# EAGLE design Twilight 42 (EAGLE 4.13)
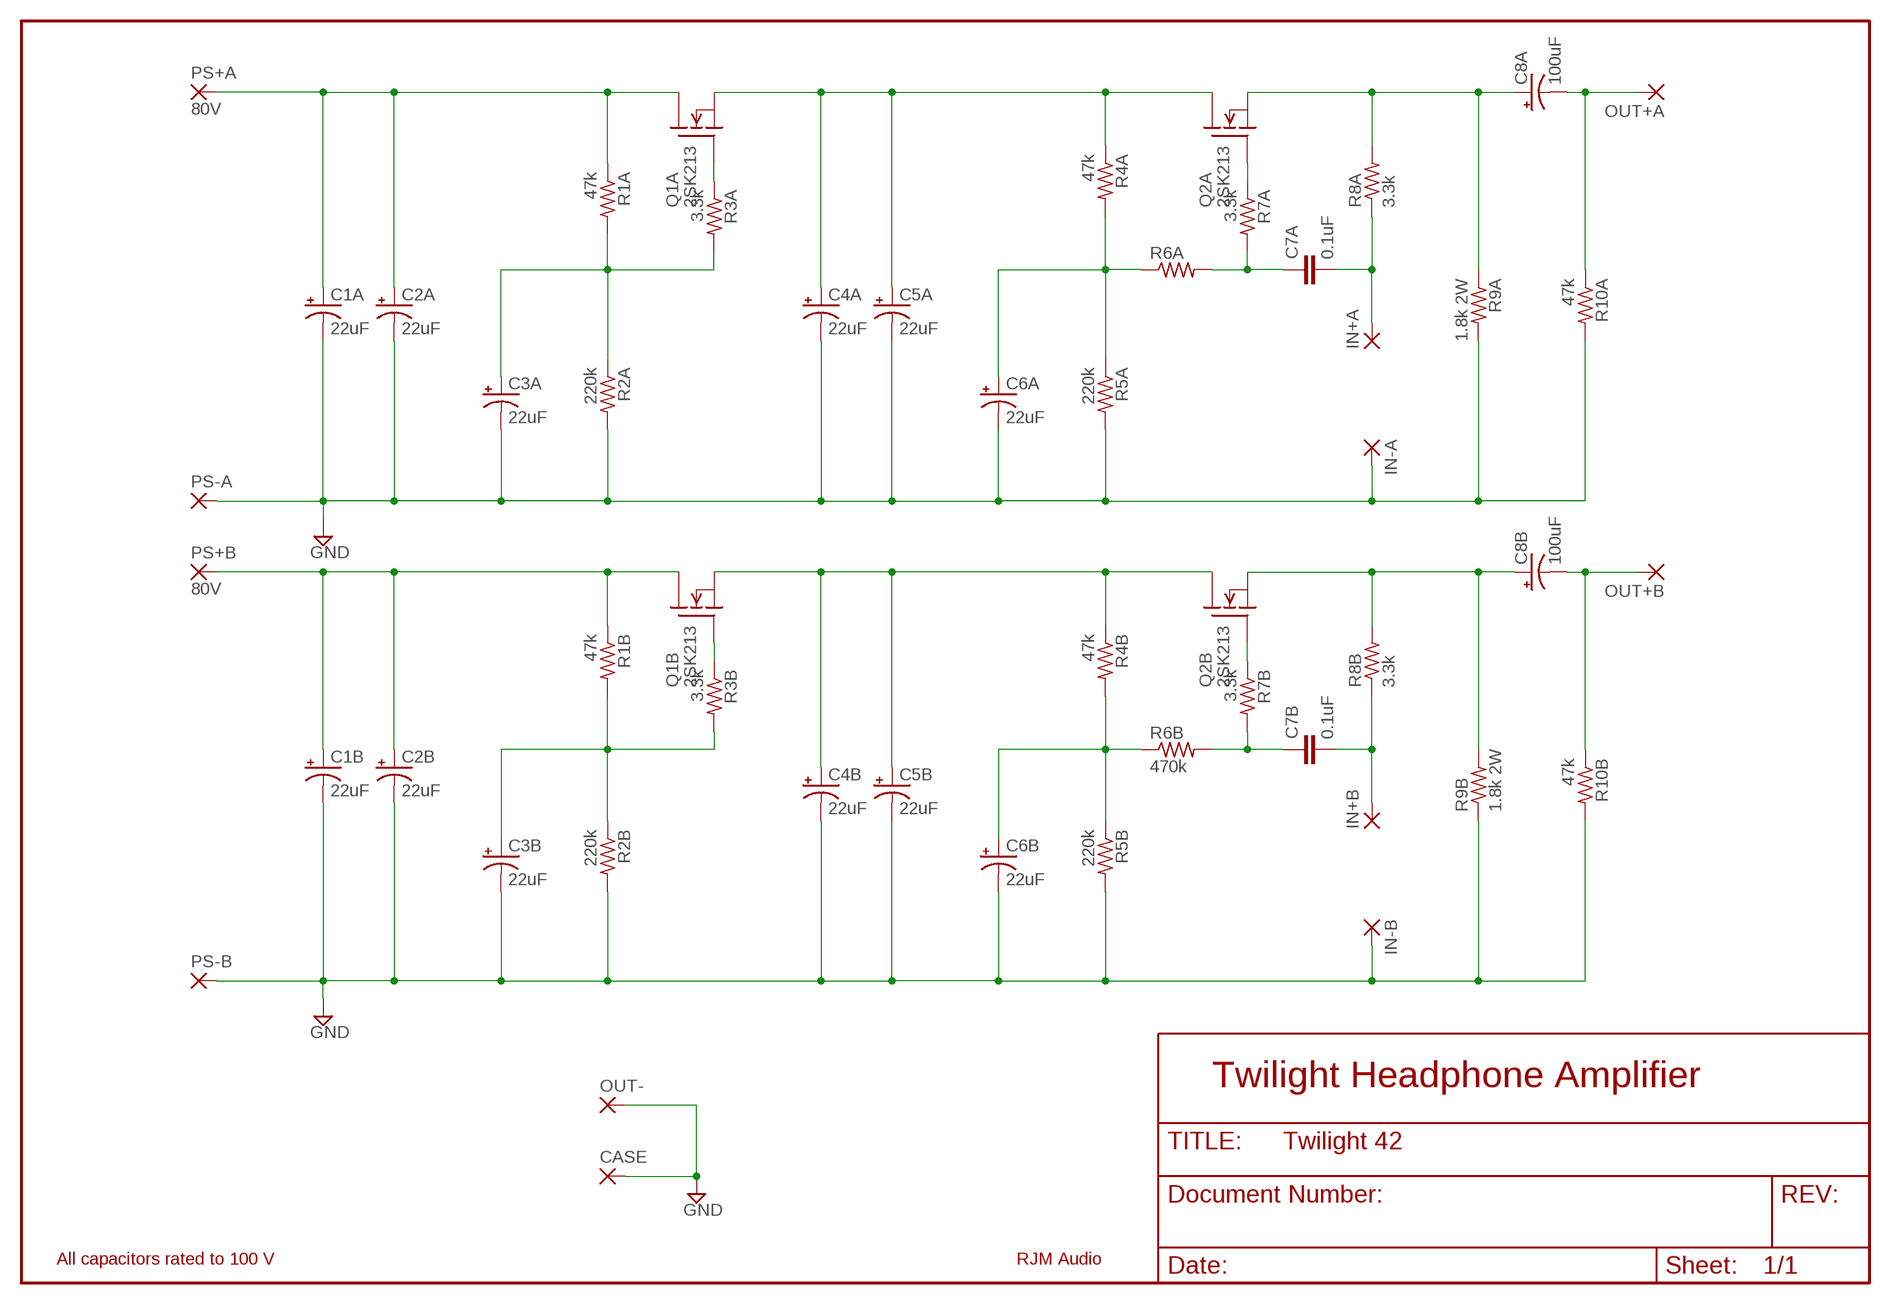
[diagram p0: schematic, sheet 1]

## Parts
C1A  22uF  CPOL-USE5-10.5  [E5-10,5]
C1B  22uF  CPOL-USE5-10.5  [E5-10,5]
C2A  22uF  CPOL-USE5-10.5  [E5-10,5]
C2B  22uF  CPOL-USE5-10.5  [E5-10,5]
C3A  22uF  CPOL-USE5-10.5  [E5-10,5]
C3B  22uF  CPOL-USE5-10.5  [E5-10,5]
C4A  22uF  CPOL-USE5-10.5  [E5-10,5]
C4B  22uF  CPOL-USE5-10.5  [E5-10,5]
C5A  22uF  CPOL-USE5-10.5  [E5-10,5]
C5B  22uF  CPOL-USE5-10.5  [E5-10,5]
C6A  22uF  CPOL-USE5-10.5  [E5-10,5]
C6B  22uF  CPOL-USE5-10.5  [E5-10,5]
C7A  0.1uF  C-EUC450-400X150RTX  [MULTICAP]
C7B  0.1uF  C-EUC450-400X150RTX  [MULTICAP]
C8A  100uF  CPOL-USE5-13  [E5-13]
C8B  100uF  CPOL-USE5-13  [E5-13]
CASE  2,54/1,1  [2,54/1,1]
IN+A  2,54/1,1  [2,54/1,1]
IN+B  2,54/1,1  [2,54/1,1]
IN-A  2,54/1,1  [2,54/1,1]
IN-B  2,54/1,1  [2,54/1,1]
OUT+A  2,54/1,1  [2,54/1,1]
OUT+B  2,54/1,1  [2,54/1,1]
OUT-  2,54/1,1  [2,54/1,1]
PS+A  80V  2,54/1,1  [2,54/1,1]
PS+B  80V  2,54/1,1  [2,54/1,1]
PS-A  2,54/1,1  [2,54/1,1]
PS-B  2,54/1,1  [2,54/1,1]
Q1A  2SK213  [TO220]
Q1B  2SK213  [TO220]
Q2A  2SK213  [TO220]
Q2B  2SK213  [TO220]
R1A  47k  R-US_0309/12W  [0309/12-WIDE]
R1B  47k  R-US_0309/12W  [0309/12-WIDE]
R2A  220k  R-US_0309/12W  [0309/12-WIDE]
R2B  220k  R-US_0309/12W  [0309/12-WIDE]
R3A  3.3k  R-US_0309/12W  [0309/12-WIDE]
R3B  3.3k  R-US_0309/12W  [0309/12-WIDE]
R4A  47k  R-US_0309/12W  [0309/12-WIDE]
R4B  47k  R-US_0309/12W  [0309/12-WIDE]
R5A  220k  R-US_0309/12W  [0309/12-WIDE]
R5B  220k  R-US_0309/12W  [0309/12-WIDE]
R6A  R-US_0309/12W  [0309/12-WIDE]
R6B  470k  R-US_0309/12W  [0309/12-WIDE]
R7A  3.3k  R-US_0309/12W  [0309/12-WIDE]
R7B  3.3k  R-US_0309/12W  [0309/12-WIDE]
R8A  3.3k  R-US_0309/12W  [0309/12-WIDE]
R8B  3.3k  R-US_0309/12W  [0309/12-WIDE]
R9A  1.8k 2W  R-US_TO-220  [CADDOCK930]
R9B  1.8k 2W  R-US_TO-220  [CADDOCK930]
R10A  47k  R-US_0309/12W  [0309/12-WIDE]
R10B  47k  R-US_0309/12W  [0309/12-WIDE]

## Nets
D1A: C3A.+ R1A.P$2 R2A.P$1 R3A.P$2
D1B: C3B.+ R1B.P$2 R2B.P$1 R3B.P$2
D2A: C6A.+ R4A.P$2 R5A.P$1 R6A.P$1
D2B: C6B.+ R4B.P$2 R5B.P$1 R6B.P$1
GA: C7A.P$5 R6A.P$2 R7A.P$2
GB: C7B.P$5 R6B.P$2 R7B.P$2
GND: C1A.- C1B.- C2A.- C2B.- C3A.- C3B.- C4A.- C4B.- C5A.- C5B.- C6A.- C6B.- CASE.1(P) IN-A.1(P) IN-B.1(P) OUT-.1(P) PS-A.1(P) PS-B.1(P) R2A.P$2 R2B.P$2 R5A.P$2 R5B.P$2 R9A.2 R9B.1 R10A.P$2 R10B.P$2
IA: C7A.P$6 IN+A.1(P) R8A.P$1
IB: C7B.P$6 IN+B.1(P) R8B.P$1
N$7: Q2B.1(G) R7B.P$1
N$12: Q1B.1(G) R3B.P$1
N$20: Q2A.1(G) R7A.P$1
N$25: Q1A.1(G) R3A.P$1
OA: C8A.- OUT+A.1(P) R10A.P$1
OB: C8B.- OUT+B.1(P) R10B.P$1
V1A: C1A.+ C2A.+ PS+A.1(P) Q1A.3(D) R1A.P$1
V1B: C1B.+ C2B.+ PS+B.1(P) Q1B.3(D) R1B.P$1
V2A: C4A.+ C5A.+ Q1A.2(S) Q2A.3(D) R4A.P$1
V2B: C4B.+ C5B.+ Q1B.2(S) Q2B.3(D) R4B.P$1
V3A: C8A.+ Q2A.2(S) R8A.P$2 R9A.1
V3B: C8B.+ Q2B.2(S) R8B.P$2 R9B.2

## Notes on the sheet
- Twilight Headphone Amplifier
- All capacitors rated to 100 V | RJM Audio

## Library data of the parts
C1A C1B C2A C2B C3A C3B C4A C4B C5A C5B C6A C6B C8A C8B = rcl:CPOL-US: POLARIZED CAPACITOR, American symbol
C7A C7B = rcl:C-EU: CAPACITOR, European symbol
CASE IN+A IN+B IN-A IN-B OUT+A OUT+B OUT- PS+A PS+B PS-A PS-B = wirepad:2,54/1,1: THROUGH-HOLE PAD
Q1A Q1B Q2A Q2B = transistor-fet:2SK213: N-channel enhancement mode MOSFET
R1A R1B R2A R2B R3A R3B R4A R4B R5A R5B R6A R6B R7A R7B R8A R8B R9A R9B R10A R10B = rcl:R-US_: RESISTOR, American symbol

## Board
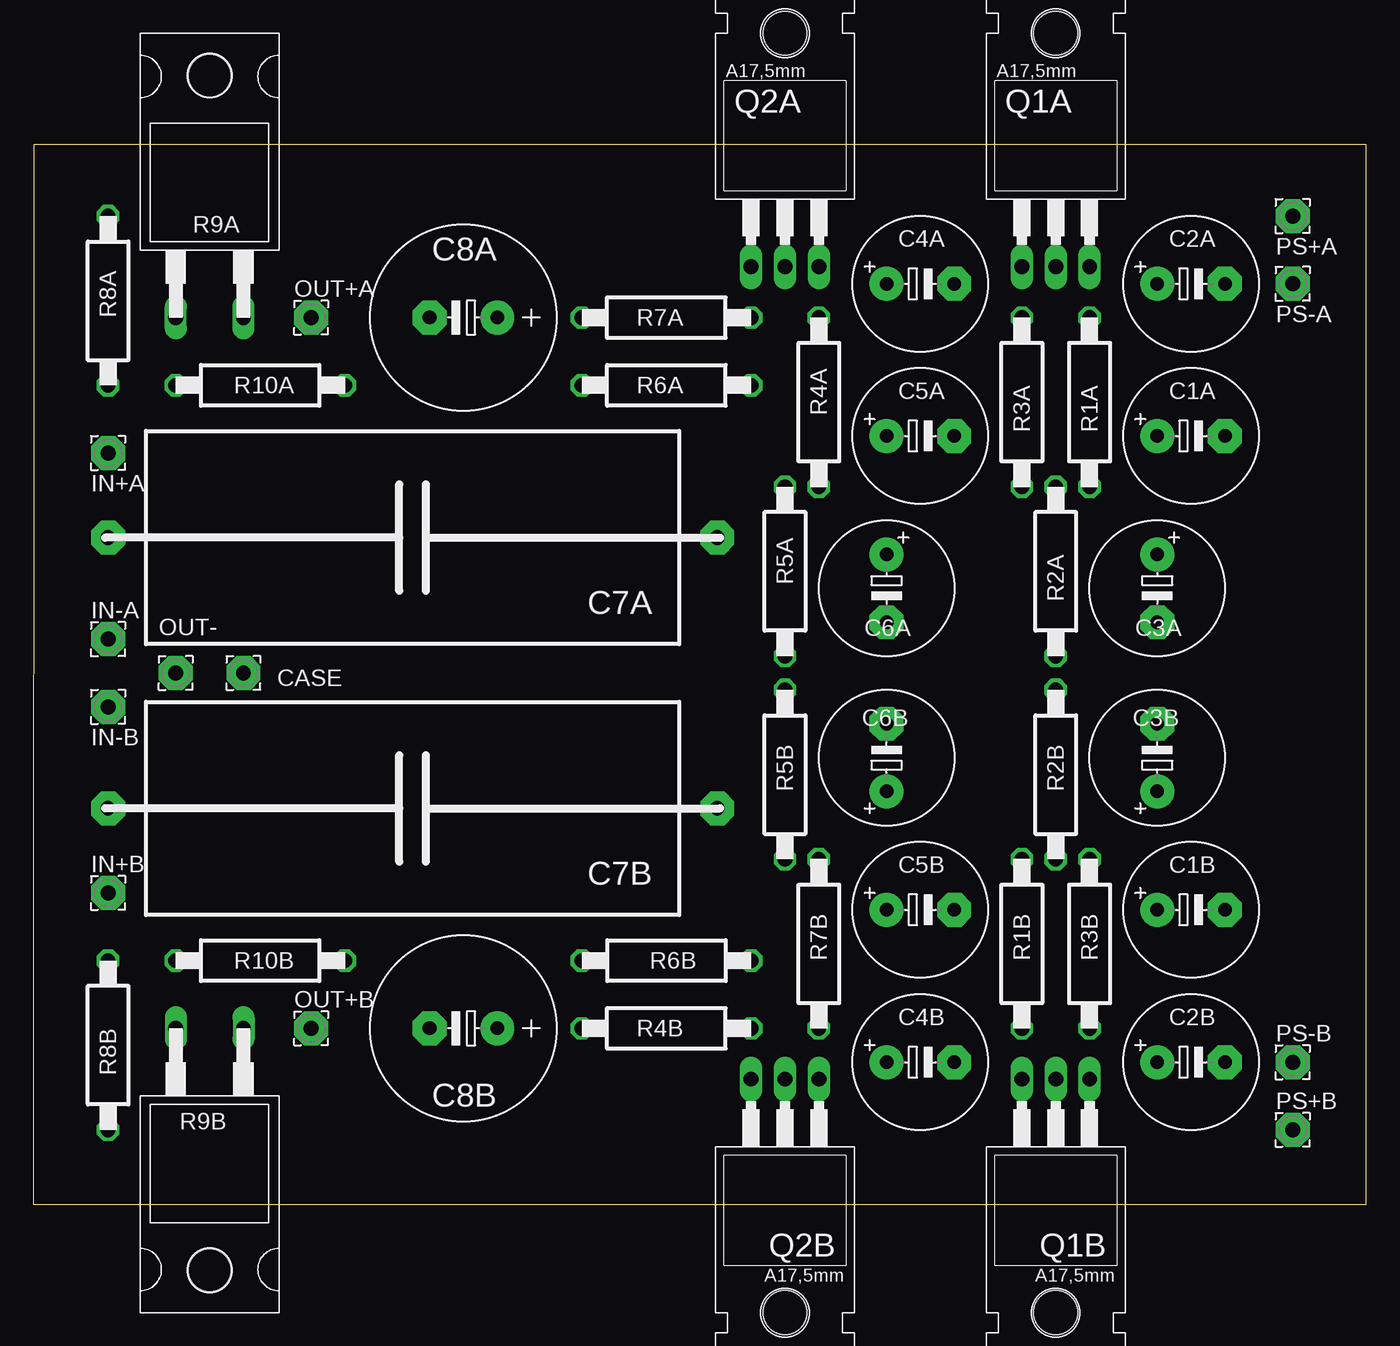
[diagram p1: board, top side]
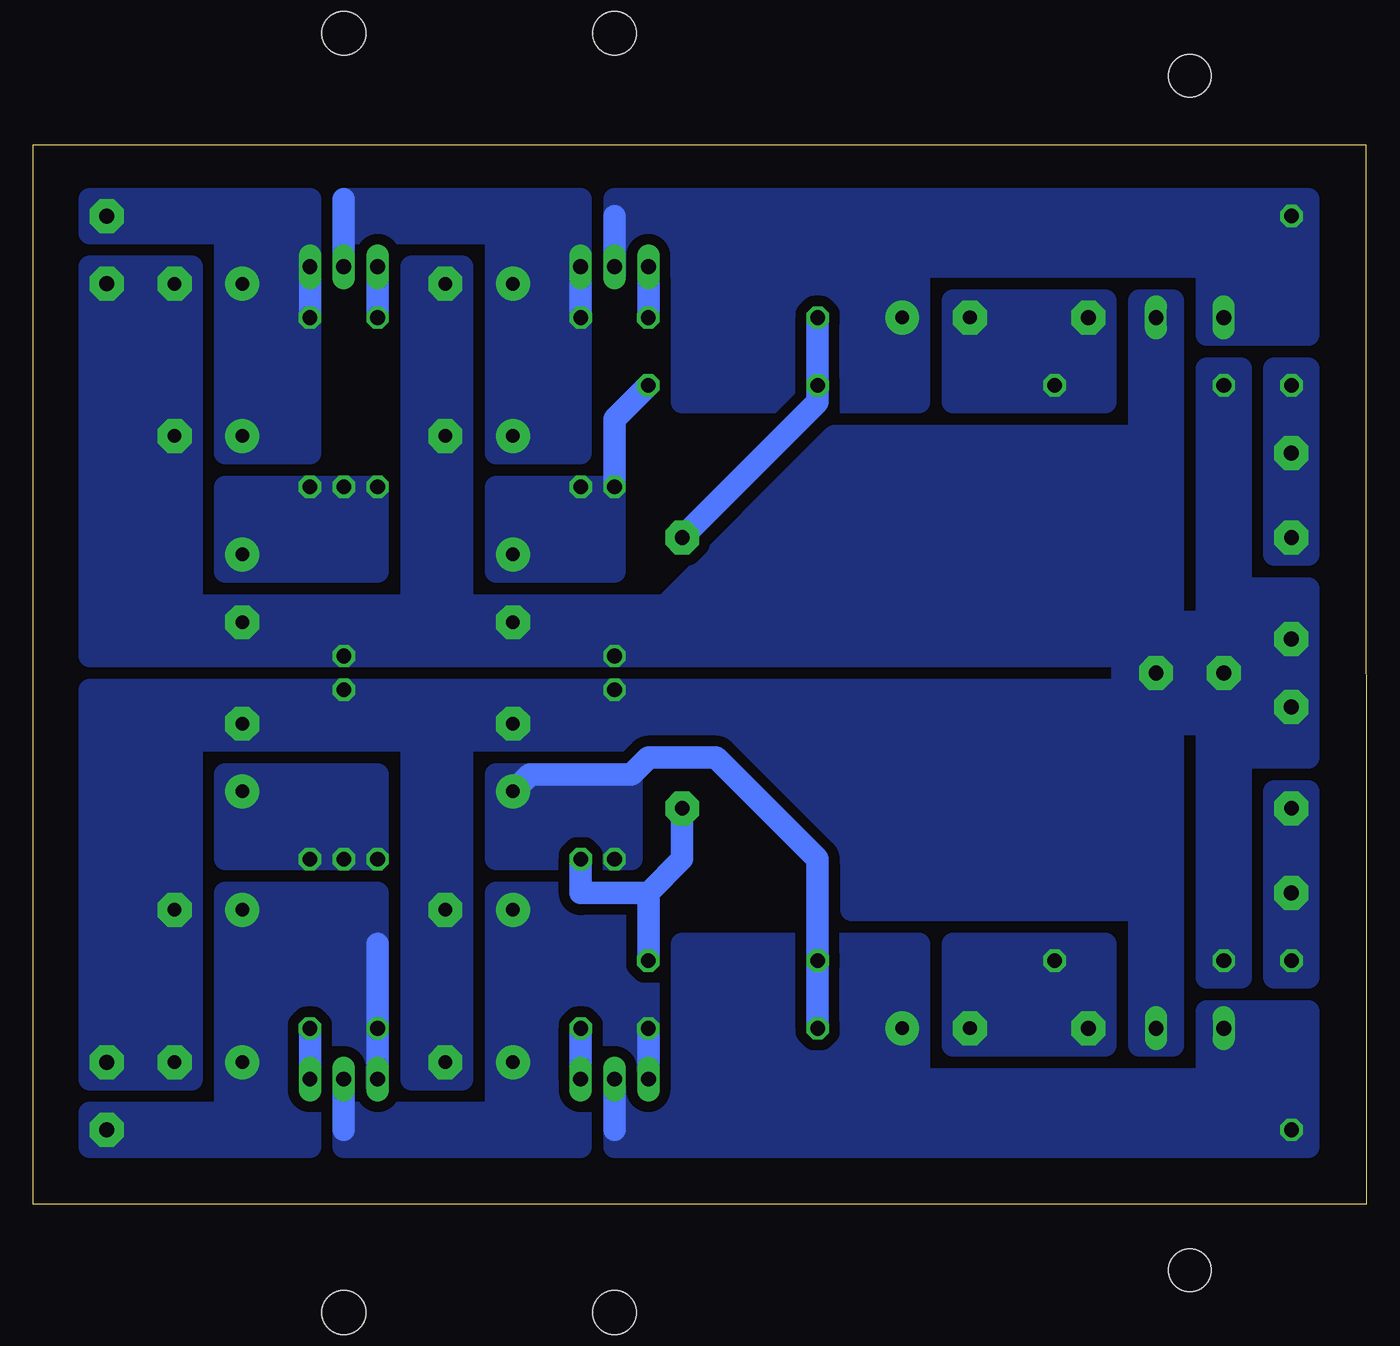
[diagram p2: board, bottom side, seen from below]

Size 100.03 x 79.51 mm. Coordinates in mm from the lower left corner, seen from the top.
Outline: 0,0 100.03,0.01 100.03,79.51 0.03,79.51 0,0
Copper layers (1*16): Top 0.035mm / dielectric 1.5mm / Bottom 0.035mm
Design rules "default": minimum track width 10mil, minimum drill 24mil, track to track 8mil, track to pad 8mil, pad to pad 8mil, via to via 8mil, smd to smd 8mil, copper to edge 40mil, drill to drill 8mil, minimum pad ring 10mil, minimum via ring 8mil, stop-mask expansion 4mil, vias tented up to drill 0mil, thermal gap 10mil

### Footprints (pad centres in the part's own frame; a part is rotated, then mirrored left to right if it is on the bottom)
E5-10,5 = drill 1.016 pad 2.54 round: + -2.54,0 | drill 1.016 pad 2.54 octagon: - 2.54,0
MULTICAP = drill 1.1 pad 2.54 octagon: P$5 -22.86,0; P$6 22.86,0
E5-13 = drill 1.016 pad 2.54 round: + -2.54,0 | drill 1.016 pad 2.54 octagon: - 2.54,0
2,54/1,1 = drill 1.118 pad 2.54 octagon: 1 0,0
TO220 = drill 1.118 long: 1 -2.54,-6.35; 2 0,-6.35; 3 2.54,-6.35 | hole 3.302: 0,11.176
0309/12-WIDE = drill 1.1 pad 1.676 octagon: P$1 -6.35,0; P$2 6.35,0
CADDOCK930 = drill 1.1 long: 1 -2.54,0; 2 2.54,0 | hole 3.2: 0,18.161

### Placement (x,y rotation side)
C1A  86.89,57.66 0 top
C1B  86.89,22.1 0 top
C2A  86.89,69.09 0 top
C2B  86.89,10.67 0 top
C3A  84.35,46.23 270 top
C3B  84.35,33.53 90 top
C4A  66.57,69.09 0 top
C4B  66.57,10.67 0 top
C5A  66.57,57.66 0 top
C5B  66.57,22.1 0 top
C6A  64.03,46.23 270 top
C6B  64.03,33.53 90 top
C7A  28.47,50.04 180 top
C7B  28.47,29.72 180 top
C8A  32.28,66.55 180 top
C8B  32.28,13.21 180 top
CASE  15.77,39.88 0 top
IN+A  5.61,56.39 0 top
IN+B  5.61,23.37 0 top
IN-A  5.61,42.42 0 top
IN-B  5.61,37.34 0 top
OUT+A  20.85,66.55 0 top
OUT+B  20.85,13.21 0 top
OUT-  10.69,39.88 0 top
PS+A  94.51,74.17 0 top
PS+B  94.51,5.59 0 top
PS-A  94.51,69.09 0 top
PS-B  94.51,10.67 0 top
Q1A  76.73,76.71 0 top
Q1B  76.73,3.05 180 top
Q2A  56.41,76.71 0 top
Q2B  56.41,3.05 180 top
R1A  79.27,60.2 270 top
R1B  74.19,19.56 90 top
R2A  76.73,47.5 270 top
R2B  76.73,32.26 90 top
R3A  74.19,60.2 270 top
R3B  79.27,19.56 90 top
R4A  58.95,60.2 270 top
R4B  47.52,13.21 180 top
R5A  56.41,47.5 270 top
R5B  56.41,32.26 90 top
R6A  47.52,61.47 180 top
R6B  47.52,18.29 0 top
R7A  47.52,66.55 180 top
R7B  58.95,19.56 90 top
R8A  5.61,67.82 90 top
R8B  5.61,11.94 270 top
R9A  13.23,66.55 0 top
R9B  13.23,13.21 180 top
R10A  17.04,61.47 180 top
R10B  17.04,18.29 180 top

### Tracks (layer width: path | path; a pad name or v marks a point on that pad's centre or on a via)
D1A
  pour Bottom (isolate 0.813, no thermals): 74.19,53.85 85.62,53.85 85.62,47.5 74.19,47.5
D1B
  pour Bottom (isolate 0.813, no thermals): 74.19,32.26 85.62,32.26 85.62,25.91 74.19,25.91
D2A
  Bottom 1.676: R6A.P$1 56.41,58.93 R5A.P$1
  pour Bottom (isolate 0.813, no thermals): 56.41,53.85 60.22,53.85 58.95,53.85 65.3,53.85 65.3,47.5 56.41,47.5
D2B
  Bottom 1.27: R4B.P$2 R6B.P$1
  Bottom 1.676: R4B.P$2 R6B.P$1 41.17,25.91 48.79,33.53 53.87,33.53 55.14,32.26 62.76,32.26 C6B.+
  pour Bottom (isolate 0.813, no thermals): 55.14,25.91 55.14,32.26 65.3,32.26 65.3,25.91
GA
  Bottom 1.676: R7A.P$2 R6A.P$2 41.17,60.2 C7A.P$5
GB
  Bottom 1.676: R7B.P$2 58.95,23.37 53.87,23.37 | R6B.P$2 53.87,23.37 | 53.87,23.37 51.33,25.91 C7B.P$5
GND
  pour Bottom (isolate 0.813, no thermals): 38.63,22.1 17.04,22.1 17.04,11.94 14.5,11.94 14.5,36.07 11.96,36.07 11.96,17.02 9.42,17.02 9.42,33.53 4.34,33.53 4.34,46.23 9.42,46.23 9.42,62.74 11.96,62.74 11.96,43.69 14.5,43.69 14.5,67.82 17.04,67.82 17.04,57.66 39.9,57.66 52.6,44.96 67.84,44.96 67.84,70.36 71.65,70.36 71.65,44.96 88.16,44.96 88.16,70.36 95.78,70.36 95.78,41.15 18.31,41.15 18.31,38.61 95.78,38.61 95.78,9.4 88.16,9.4 88.16,34.8 71.65,34.8 71.65,9.4 67.84,9.4 67.84,34.8 47.52,34.8 38.63,25.91
IA
  pour Bottom (isolate 0.813, no thermals): 4.34,62.74 6.88,62.74 6.88,48.77 4.34,48.77
IB
  pour Bottom (isolate 0.813, no thermals): 4.34,30.99 6.88,30.99 6.88,17.02 4.34,17.02
N$7
  Bottom 1.676: Q2B.1 R7B.P$1
N$12
  Bottom 1.676: Q1B.1 R3B.P$1
N$20
  Bottom 1.676: R7A.P$1 Q2A.1
N$25
  Bottom 1.676: R3A.P$1 Q1A.1
OA
  pour Bottom (isolate 0.813, no thermals): 19.58,60.2 31.01,60.2 31.01,67.82 19.58,67.82
OB
  pour Bottom (isolate 0.813, no thermals): 19.58,11.94 19.58,19.56 31.01,19.56 31.01,11.94
V1A
  Bottom 1.676: R1A.P$1 Q1A.3
  pour Bottom (isolate 0.813, no thermals): 79.27,56.39 79.27,75.44 95.78,75.44 95.78,72.9 85.62,72.9 85.62,56.39
V1B
  Bottom 1.27: Q1B.3 R1B.P$1 Q1B.3
  Bottom 1.676: Q1B.3 74.19,19.56
  pour Bottom (isolate 0.813, no thermals): 85.62,6.86 95.78,6.86 95.78,4.32 79.27,4.32 79.27,9.4 74.19,9.4 74.19,23.37 85.62,23.37
V2A
  Bottom 1.676: R4A.P$1 Q2A.3 | Q1A.2 76.73,75.44
  pour Bottom (isolate 0.813, no thermals): 58.95,75.44 58.95,56.39 65.3,56.39 65.3,72.9 76.73,72.9 76.73,75.44
V2B
  Bottom 1.27: Q2B.3 R4B.P$1
  Bottom 1.676: 76.73,5.59 Q1B.2 | Q2B.3 R4B.P$1
  pour Bottom (isolate 0.813, no thermals): 53.87,23.37 65.3,23.37 65.3,6.86 76.73,6.86 76.73,4.32 58.95,4.32 58.95,10.67 53.87,10.67
V3A
  Bottom 1.676: Q2A.2 56.41,74.17
  pour Bottom (isolate 0.813, no thermals): 4.34,65.28 4.34,75.44 56.41,75.44 56.41,70.36 51.33,70.36 51.33,60.2 33.55,60.2 33.55,70.36 11.96,70.36 11.96,65.28
V3B
  Bottom 1.676: 56.41,5.59 Q2B.2
  pour Bottom (isolate 0.813, no thermals): 4.34,4.32 56.41,4.32 56.41,8.13 51.33,8.13 51.33,19.56 33.55,19.56 33.55,9.4 11.96,9.4 11.96,14.48 4.34,14.48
